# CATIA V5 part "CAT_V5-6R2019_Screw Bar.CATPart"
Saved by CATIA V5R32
Part number: Screw Bar
Bounding box of the stored display mesh (mm): x -3 to 3, y -52 to 52, z -2.853 to 2.853
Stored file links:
  D:\PROJECTS\Project 2022\CATIA V5 6R 2022\Resources\Tutorial Files\c16_catia_v5_6r2022_tut\Bench vice\CAT_V5-6R2019_Screw Bar.CATPart
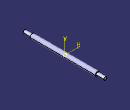
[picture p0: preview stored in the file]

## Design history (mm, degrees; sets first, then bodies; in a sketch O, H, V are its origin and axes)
Body1 (main body)
  Sketch1 on zx-plane, origin (0, 0, 0), H (-1, 0, 0), V (0, 0, 1)
    circle A1 centre (0, 0) radius 2
    radius A1 = 2
  Sketch2 on zx-plane, origin (0, 0, 0), H (-1, 0, 0), V (0, 0, 1)
    circle A1 centre (0, 0) radius 3
    radius A1 = 3
  Pad1: profile Sketch1, direction (0, 1, 0), length 52, mirrored extent
  Pad2: profile Sketch2, direction (0, 1, 0), length 42, mirrored extent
